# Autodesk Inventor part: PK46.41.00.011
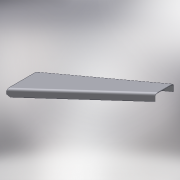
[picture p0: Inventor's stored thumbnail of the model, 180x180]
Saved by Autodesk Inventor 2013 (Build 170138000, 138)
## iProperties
Created: 2005-07
Part Number: PK46.41.00.011
Material: Steel, Mild
Document SubType Name: Modeling
Designer: PVitaliy
Manufacturer: Standard
Standards Organization: Custom
Density: 7.86 g/cm^3
Mass: 1058.63 g
Surface Area: 929.402 cm^2
Volume: 134.686 cm^3
Author: PVitaliy
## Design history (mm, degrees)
derived "PK46.41.00.113-01.ipt"
body "Solid1"
tag "TaggingFeature2"
feature "DerivedBody::PK46.41.00.113-01.ipt" dims "d0" = 10
